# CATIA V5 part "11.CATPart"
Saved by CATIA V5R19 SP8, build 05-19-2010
Part number: 11
Bounding box of the stored display mesh (mm): x -120 to 120, y -160 to 60, z -30 to 190
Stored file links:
  G:\EU_thinkMotion\CFAO_2010\MMS_groupe3\MMS_groupe3\A reprendre\bblot\BLOT\11.CATPart
  J:\CFAO_IFMA\Amortisseur.CATProduct
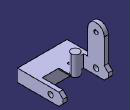
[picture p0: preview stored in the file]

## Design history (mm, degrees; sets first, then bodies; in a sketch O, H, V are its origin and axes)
External parameters (linked from other documents)
  `External.Diamètre 9-10` = 50 mm
  `External.Diamètre 9-11` = 20 mm
Set1
  Plane1 "Dessus 9": stored without definition
  Plane2: stored without definition
  DatumCurve1
  DatumCurve2
  Line1: stored without definition
Set2
  Plane3 "Plan dessous": linked copy from another document
  Plane4 "Plan face 11": linked copy from another document
  Plane5 "Plan 9-10 droite": linked copy from another document
  Plane6 "Plan 9-10 gauche": linked copy from another document
  Plane7 "Plan profondeur 9-10": linked copy from another document
  Plane8 "Plan 9-11": linked copy from another document
  Line2 "ab": linked copy from another document
  Line3 "ar": linked copy from another document
  Line4: linked copy from another document
Body1 (main body)
  Sketch1 on Plane3, origin (0, 0, -30), H (1, 0, 0), V (0, 1, 0)
    point P1 (100, 60)
    line L1 (100, 60) -> (120, 60)
    line L2 (120, 60) -> (120, -160)
    line L3 (120, -160) -> (-120, -160)
    line L4 (-120, -160) -> (-120, 60)
    point P5 (-120, 60)
    line L5 (-120, 60) -> (-100, 60)
    line L6 (-100, 60) -> (-100, -60)
    line L7 (-100, -60) -> (100, -60)
    line L8 (100, -60) -> (100, 60)
    point P9 (100, 60)
    reference intersected line E1 through (0, 60) direction (-1, 0) from Plane4
    reference intersected line E2 through (-100, 0) direction (0, 1) from Plane5
    reference intersected line E3 through (100, 0) direction (0, 1) from Plane6
    reference intersected line E4 through (0, -60) direction (-1, 0) from Plane7
    distance L7 L3 = 100
    length L5 = 20
    length L1 = 20
    horizontal: L1 H, L3 H, L5 H, L7 H
    vertical: L2 V, L4 V, L6 V, L8 V
    coincidence: P5 L1, P1 P9, E1 L5, L6 E2, L8 E3, L7 E4
  Pad1: profile Sketch1, direction (0, 0, 1), up to Plane8
  Chamfer1: length 20, angle 45, on edge [end face of Pad1 | face of Pad1 from Sketch1.L1]; edge [end face of Pad1 | face of Pad1 from Sketch1.L5]; edge [start face of Pad1 | face of Pad1 from Sketch1.L5]; edge [start face of Pad1 | face of Pad1 from Sketch1.L1]
  Sketch2 on face of Pad1 from Sketch1.L2, origin (120, -46.0776, 15.819), H (0, 1, 0), V (0, 0, 1)
    point P1 (46.0776, -15.819)
    reference projected point E1 (46.0776, -15.819) from Line2
    coincidence: P1 E1
  Hole1: placed by Sketch2, at (120, 0, 0) direction (-1, 0, 0), diameter 25 {= `External.Diamètre 9-10` /2}, through (limit type 3)
  Sketch3 on end face of Pad1, origin (0, 0, 30), H (1, 0, 0), V (0, 1, 0)
    line L1 (-20, 0) -> (-20, -60)
    line L2 (-20, -60) -> (20, -60)
    line L3 (20, -60) -> (20, 0)
    arc A1 centre (0, 0) radius 20 from (20, 0) to (-20, 0) ccw
    point P5 (0, 0)
    reference projected point E1 (0, 0) from Line3
    reference projected line E2 (-100, -60) -> (100, -60) from edge [end face of Pad1 | face of Pad1 from Sketch1.L7]
    radius A1 = 20 {= `External.Diamètre 9-11`}
    vertical: L1 V, L3 V
    horizontal: L2 H
    tangency: A1 L1, A1 L3
    coincidence: P5 E1, L2 E2
  Pad2: profile Sketch3, direction (0, 0, -1), length 5
  Sketch4 on face of Pad2, origin (0, 0, 30), H (1, 0, 0), V (0, 1, 0)
    circle A1 centre (0, 0) radius 20
    reference projected arc E1 centre (0, 0) radius 20 from (20, 0) to (-20, 0) ccw from edge [face of Pad2 from Sketch3.A1 | start face of Pad2]
    coincidence: A1 E1
  Pad3: profile Sketch4, direction (0, 0, 1), up to Plane1, offset 10
  Sketch5 on face of Pad1 from Sketch1.L6, origin (-100, 0, 0), H (0, 1, 0), V (0, 0, 1)
    line L1 (-40, 30) -> (-40, 150)
    arc A1 centre (0, 150) radius 40 from (-40, 150) to (40, 150) cw
    point P3 (0, 150)
    line L2 (40, 150) -> (40, 30)
    line L3 (40, 30) -> (-40, 30)
    reference projected line E1 (60, 30) -> (-60, 30) from edge [face of Pad2 | face of Pad1 from Sketch1.L6]
    reference projected point E2 (0, 150) from Line4
    reference projected point E3 (40, 30) from edge [end face of Pad1 | face of Chamfer1]
    circle A2 centre (0, 150) radius 10
    point P6 (0, 160)
    radius A2 = 10
    vertical: L1 V, L2 V
    tangency: A1 L1, L2 A1
    horizontal: L3 H
    coincidence: L3 E1, P3 E2, L2 E3, A2 P6, P6 V
  Pad4: profile Sketch5, direction (-1, 0, 0), up to face of Pad1 from Sketch1.L4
